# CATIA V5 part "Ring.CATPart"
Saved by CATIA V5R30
Part number: Part1.1
Bounding box of the stored display mesh (mm): x -5 to 5, y -15 to 15, z -15 to 15
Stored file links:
  D:\PROJECTS\CATIA V56R 2020\Resources\Parts File\c12_catia_v5_6r2020_prt\c12_catia_v5-6r2020 figr_12-15\Ring.CATPart
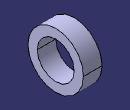
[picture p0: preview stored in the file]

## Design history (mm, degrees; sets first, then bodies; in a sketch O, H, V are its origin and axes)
Body1 (main body)
  Sketch1 on yz-plane, origin (0, 0, 0), H (0, 1, 0), V (0, 0, 1)
    circle A1 centre (0, 0) radius 15
    circle A2 centre (0, 0) radius 10
    radius A1 = 15
    radius A2 = 10
  Pad1: profile Sketch1, direction (1, 0, 0), length 5, mirrored extent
